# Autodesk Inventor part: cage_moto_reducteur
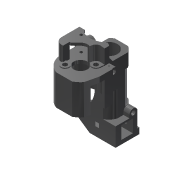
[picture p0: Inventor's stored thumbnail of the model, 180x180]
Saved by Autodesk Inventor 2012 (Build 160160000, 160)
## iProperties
Created: 2011-07
Part Number: cage_moto_reducteur
Document SubType Name: Modeling
Designer: didierf
Density: 1.13 g/cm^3
Material: Nylon - 6/6
Mass: 1.97671 g
Surface Area: 29.4498 cm^2
Volume: 1.7493 cm^3
entraxe_moteur_mobile: 6,000 mm
entraxe_mobile_roue_vis: 7,950 mm
entraxe_moteur_roue_vis: 12,000 mm
Author: didierf
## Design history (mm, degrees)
sketch "Esquisse1" dims "d1" = 12 (= 2 x entraxe_moteur_mobile), "d3" = 15.9 (= 2 x entraxe_mobile_roue_vis), "d4" = 24 (= 2 x entraxe_moteur_roue_vis)
  geometry: C1 r 2.5 at (2.847, -0.387); C2 r 0.5 at (-1.852, 3.344); C3 r 3.14 at (-9.14, 0.167); 3 further points
  constraints: 3 centre point, 3 coincident, 9 other
  dimensions: "d0" = 5 diameter of C1; "d2" = 1 diameter of C2; "d5" = 6.28 diameter of C3
sketch "Esquisse2" dims "d66" = 15.9 (= 2 x entraxe_mobile_roue_vis), "d67" = 12 (= 2 x entraxe_moteur_mobile), "d68" = 24 (= 2 x entraxe_moteur_roue_vis)
  geometry: L1 (-154.32, -14.987)-(-180.391, -5.63); L2 (-180.391, -5.63)-(-170.126, 22.971); L3 (-170.126, 22.971)-(-144.055, 13.613); L4 (-144.055, 13.613)-(-154.32, -14.987); L5 (-31.79, 28.076)-(-25.53, 28.076); L6 (-25.53, 28.076)-(-25.53, 27.076); L7 (-25.53, 27.076)-(-31.79, 27.076); L8 (-31.79, 27.076)-(-31.79, 28.076); L9 (-31.79, 28.076)-(-25.53, 27.076); L10 (-24.13, 32.056)-(-24.13, 23.306); L11 (-32.96, 32.056)-(-32.96, 23.306); L12 (-28.66, 27.576)-(-28.66, 30.706); L13 (-29.16, 24.446)-(-29.16, 30.706); L14 (-29.16, 30.706)-(-28.66, 30.706); L15 (-32.96, 32.056)-(-24.13, 32.056); L16 (-32.96, 23.306)-(-24.13, 23.306); L17 (-19.93, 38.152)-(-19.93, 8.926); L18 (-33.93, 33.977)-(-33.93, 8.926); L19 (-33.93, 8.926)-(-19.93, 8.926); L20 (-67.292, 19.43)-(-62.292, 19.43); L21 (-62.292, 19.43)-(-62.292, 18.43); L22 (-62.292, 18.43)-(-67.292, 18.43); L23 (-67.292, 18.43)-(-67.292, 19.43); L24 (-67.292, 19.43)-(-62.292, 18.43); L25 (-29.16, 24.446)-(-27.655, 24.446); C1 r 2.5 at (-60.831, 26.959); C2 r 0.5 at (-31.23, 20.052); C3 r 2.5 at (-27.128, 15.674); A1 r 3.17 centre (-28.66, 27.576) between (-31.79, 27.076) and (-29.16, 30.706); 4 further points
  constraints: 42 end point, 10 parallel, 7 perpendicular, 4 centre point, 3 coincident, 3 point on circle, 2 horizontal, 2 midpoint, 14 other
  dimensions: "d7" = 27.7 distance of L2.end L3.end; "d46" = 1 distance of L7.end L5.start; "d47" = 6.26 distance of L5.start L5.end; "d48" = 1.4 distance between parallel lines of L10 L6; "d49" = 8.83 distance between parallel lines of L11 L10; "d50" = 0.5 distance between parallel lines of L12 L13; "d51" = 1.35 distance between parallel lines of L15 L14; "d54" = 8.75 distance between parallel lines of L16 L15; "d55" = 4.2 distance between parallel lines of L17 L10; "d56" = 14 distance between parallel lines of L18 L17; "d58" = 23.13 distance between parallel lines of L19 L15; "d63" = 5 diameter of C1; "d64" = 5 distance of L21.end L22.end; "d65" = 1 distance of L20.end L21.end; "d69" = 2.7 distance from line of L18 C2.centre; "d275" = 5 diameter of C3; "d277" = 1 diameter of C2
  node "Image1"
sketch "Esquisse3"
  geometry: L1 (-32.96, 32.056)-(-24.13, 32.056) reference; L2 (-32.96, 32.056)-(-32.96, 23.306) reference; L3 (-32.96, 23.306)-(-24.13, 23.306) reference; L4 (-24.13, 32.056)-(-24.13, 23.306) reference
  dimensions: "d73" = 8.83 distance of L1.start L1.end (derived); "d74" = 8.75 distance of L1.start L2.end (derived)
extrude "corps_vis" new body sketch "Esquisse3" distance "d71" = 25.84; taper "d72" = 0 deg
sketch "Esquisse4"
  geometry: C1 r 3.175 at (-28.66, 27.576) reference
extrude "alésage roulements" cut sketch "Esquisse4" distance "d75" = 16.9; taper "d76" = 0 deg
sketch "Esquisse5"
  geometry: L1 (-24.13, 32.056)-(-24.13, 23.306) reference; L2 (-32.96, 32.056)-(-24.13, 32.056) reference; L3 (-32.96, 23.306)-(-32.96, 32.056) reference; L4 (-24.13, 23.306)-(-32.96, 23.306) reference; C1 r 3.17 at (-28.66, 27.576); C2 r 3 at (-28.66, 27.576); C3 r 3.175 at (-28.66, 27.576) reference
  constraints: 2 centre point, 1 coincident
  dimensions: "d289" = 6 diameter of C2
extrude "alésage butée roul" cut sketch "Esquisse5" distance "d79" = 19; taper "d80" = 0 deg
sketch "Esquisse6"
  geometry: L1 (-24.13, 32.056)-(-24.13, 23.306) reference; L2 (-32.96, 32.056)-(-24.13, 32.056) reference; L3 (-32.96, 23.306)-(-32.96, 32.056) reference; L4 (-24.13, 23.306)-(-32.96, 23.306) reference; C1 r 3.17 at (-28.66, 27.576); C2 r 1.98 at (-28.66, 27.576); C3 r 3.175 at (-28.66, 27.576) reference
  constraints: 2 centre point, 1 coincident
  dimensions: "d81" = 3.96 diameter of C2
extrude "alésage extrem vis" cut sketch "Esquisse6" stored distance "d82" = 19; taper "d83" = 0 deg
sketch "Esquisse9"
  geometry: L1 (0, 0)-(0, 25.84) reference; L2 (0, 25.84)-(0, 27.34); L3 (0, 27.34)-(-4, 27.34); L4 (-4, 27.34)-(-4, 0); L5 (0, 0)-(-4, 0)
  constraints: 8 end point, 2 perpendicular, 1 collinear, 1 parallel
  dimensions: "d91" = 4 distance between parallel lines of L4 L2; "d92" = 27.34 distance between parallel lines of L3 L5
extrude "platine_fixation" join sketch "Esquisse9" distance "d93" = 4; taper "d94" = 0 deg
sketch "Esquisse10"
  geometry: L1 (12.83, 0)-(4, 0) reference; L2 (2.832, -7.632)-(2.832, 0); L3 (16.832, -7.632)-(16.832, -2.75); L4 (7.552, -14.25)-(13.36, -14.25); L5 (4, 8.75)-(12.83, 8.75) reference; L6 (12.83, 8.75)-(12.83, 0) reference; L7 (12.83, 0)-(12.83, -0.757); L8 (16.832, -2.75)-(15.032, -2.75); L9 (15.032, -2.75)-(15.032, -2.227); L10 (4, 0)-(2.832, 0); L11 (9.832, -7.632)-(20.481, -7.632); L12 (16.832, -7.632)-(15.742, -12.25); C1 r 2.5 at (9.832, -7.632) reference; A1 r 7.5 centre (9.832, -7.632) between (13.36, -14.25) and (15.742, -12.25); A2 r 7 centre (9.832, -7.632) between (2.832, -7.632) and (7.552, -14.25); A3 r 7.5 centre (9.832, -7.632) between (15.032, -2.227) and (12.83, -0.757)
  constraints: 18 end point, 6 point on circle, 3 centre point, 3 perpendicular, 2 collinear, 2 parallel, 1 coincident, 1 point on line, 1 tangent
  dimensions: "d96" = 14 distance between parallel lines of L3 L2; "d97" = 23 distance between parallel lines of L4 L5; "d99" = 7.5 radius of A1; "d100" = 7 radius of A2; "d102" = 11.5 distance between parallel lines of L8 L4; "d103" = 7.5 radius of A3; "d104" = 1.8 distance between parallel lines of L3 L9; "d108" = 2 distance from line of L12.end L4
extrude "cage moteur" join sketch "Esquisse10" distance "d105" = 11.2; taper "d106" = 0 deg
sketch "Esquisse11" dims "d126" = 8
  geometry: L1 (5.232, -14.032)-(5.832, -14.032); L2 (5.832, -14.032)-(5.832, -11.632); L3 (5.832, -11.632)-(2.832, -11.632); L4 (2.832, -11.632)-(2.832, -14.032); L5 (14.332, -5.632)-(14.332, -7.321); L6 (15.032, -6.75)-(15.032, -6.227); L7 (7.552, -18.25)-(13.36, -18.25); L8 (16.832, -11.632)-(16.832, -6.75); L9 (2.832, -4)-(2.832, -11.632); L10 (5.832, -11.632)-(2.832, -11.632); L11 (12.83, -4.757)-(12.83, -4); L12 (9.832, -11.632)-(12.661, -8.803); L13 (12.834, -7.163)-(14.332, -7.321); L14 (9.773, -6.573)-(10.012, -9.138); L15 (11.045, -8.469)-(10.862, -9.354); L16 (4, 0)-(0, 0) reference; L17 (0, -4)-(0, 0) reference; L18 (2.832, -4)-(0, -4) reference; L19 (2.832, -4)-(2.832, -11.632) reference; L20 (7.552, -18.25)-(13.36, -18.25) reference; L21 (15.742, -16.25)-(16.832, -11.632) reference; L22 (16.832, -11.632)-(16.832, -6.75) reference; L23 (16.832, -6.75)-(15.032, -6.75) reference; L24 (15.032, -6.75)-(15.032, -6.227) reference; L25 (12.83, -4.757)-(12.83, -4) reference; L26 (12.83, -4)-(4, -4) reference; L27 (4, -4)-(4, 0) reference; C1 r 3.17 at (8.3, 0.27); C2 r 0.906 at (-111.833, -48.822); C3 r 0.735 at (-104.635, -44.629); C4 r 2.5 at (9.832, -11.632) reference; A1 r 2.4 centre (5.232, -11.632) between (2.832, -11.632) and (5.232, -14.032); A2 r 7.5 centre (9.832, -11.632) between (15.032, -6.227) and (12.83, -4.757); A3 r 1.65 centre (12.661, -8.803) between (12.834, -7.163) and (11.045, -8.469); A4 r 7 centre (9.832, -11.632) between (2.832, -11.632) and (5.832, -17.376); A5 r 7 centre (8.3, 0.27) between (9.773, -6.573) and (13.06, -4.862); A6 r 7.5 centre (9.832, -11.632) between (14.332, -5.632) and (13.06, -4.862); A7 r 2.5 centre (9.832, -11.632) between (10.012, -9.138) and (10.862, -9.354); A8 r 2.5 centre (9.832, -11.632) between (10.862, -9.354) and (10.012, -9.138); A9 r 7 centre (9.832, -11.632) between (2.832, -11.632) and (7.552, -18.25) reference; A10 r 7.5 centre (9.832, -11.632) between (13.36, -18.25) and (15.742, -16.25) reference; A11 r 7.5 centre (9.832, -11.632) between (15.032, -6.227) and (12.83, -4.757) reference
  constraints: 32 end point, 17 point on circle, 11 centre point, 5 coincident, 2 parallel, 2 perpendicular, 2 point on line, 2 tangent, 1 collinear, 1 horizontal, 3 other
  dimensions: "d114" = 2.5 distance between parallel lines of L8 L5; "d116" = 0 distance between parallel lines of L4 L9; "d117" = 3 distance of L2.end L3.end; "d118" = 2.4 distance of L3.end L4.end; "d119" = 2.4 distance between parallel lines of L10 L1; "d120" = 2.4 radius of A1; "d124" = 4.21821 distance between parallel lines of L1 L7; "d128" = 45 deg angle of L8 L12; "d129" = 3.3 diameter of A3; "d143" = 14 diameter of A5; "d144" = 1.68908 distance of L5.start L5.end
extrude "piliers" join sketch "Esquisse11" distance "d122" = 4.5; taper "d123" = 0 deg
sketch "Esquisse12"
  geometry: L1 (5.832, -11.632)-(6.332, -11.632); L2 (14.332, -7.321)-(12.834, -7.163) reference; L3 (5.832, -14.032)-(5.232, -14.032) reference; L4 (2.832, -11.632)-(2.832, -5.032); L5 (2.832, -5.032)-(4.832, -5.032); L6 (5.832, -11.632)-(5.832, -14.032) reference; L7 (14.332, -7.321)-(14.332, -5.632); L8 (6.332, -11.632)-(8.046, -9.882); L9 (13.06, -4.862)-(14.332, -5.632); L10 (11.045, -8.469)-(10.862, -9.354) reference; C1 r 3.17 at (8.3, 0.27) reference; A1 r 2.4 centre (5.232, -11.632) between (2.832, -11.632) and (5.232, -14.032) reference; A2 r 1.65 centre (12.661, -8.803) between (12.834, -7.163) and (11.045, -8.469) reference; A3 r 7 centre (8.3, 0.27) between (9.773, -6.573) and (13.06, -4.862) reference; A4 r 7 centre (8.3, 0.27) between (6.139, -6.388) and (13.06, -4.862); A5 r 7.5 centre (9.832, -11.632) between (14.332, -5.632) and (13.06, -4.862) reference; A6 r 2 centre (6.756, -4.486) between (4.832, -5.032) and (6.139, -6.388); A7 r 2.5 centre (9.832, -11.632) between (10.862, -9.354) and (10.012, -9.138) reference; A8 r 2.5 centre (9.832, -11.632) between (10.862, -9.354) and (8.046, -9.882); 1 further point
  constraints: 13 end point, 9 point on circle, 3 centre point, 3 tangent, 2 coincident, 1 horizontal, 1 parallel, 1 perpendicular, 1 point on line
  dimensions: "d133" = 0.5 distance of L1.start L1.end; "d137" = 9 distance between parallel lines of L5 L3; "d147" = 2 radius of A6; "d148" = 2 distance of L4.end L5.end
extrude "platine" join sketch "Esquisse12" distance "d138" = 1; taper "d139" = 0 deg
sketch "Esquisse14"
  geometry: L1 (-27.34, 0)-(-25.84, 0) reference; L2 (-25.84, 8.75)-(-25.84, 0) reference; L3 (-27.34, 0)-(-25.84, 1.1)
  constraints: 2 end point, 1 point on line
  dimensions: "d153" = 1.1 vertical distance of L1.start L3.end
extrude "chanfrein" join sketch "Esquisse14" stored distance "d154" = 1; taper "d155" = 0 deg
sketch "Esquisse13"
  geometry: L1 (0, 0)-(11.2, 0) reference; L2 (0, 0)-(0, 0.523) reference; L3 (1.5, 11.5)-(1.5, 3.85) reference; L4 (0, 0.523)-(11.2, 0.523) reference; L5 (4.45, 0.523)-(1.55, 0.523); L6 (4.45, 2.1)-(4.45, 0.523); L7 (4.45, 0)-(4.45, -0.154); L8 (1.55, 2.1)-(1.55, 0.523); L9 (1.05, 0)-(1.05, -0.345); L10 (27.34, 11.5)-(1.5, 11.5) reference; L11 (27.34, 11.5)-(27.34, 2.75) reference; L12 (27.34, 2.75)-(11.2, 2.75) reference; L13 (20.54, 2.75)-(20.54, 7.85); L14 (19.5, 7.85)-(20.54, 7.85); L15 (25.19, 10.75)-(19.5, 10.75); L16 (20.54, 2.75)-(27.34, 2.75); L17 (27.34, 2.75)-(27.34, 10.75); L18 (25.19, 10.75)-(25.19, 11.5); L19 (25.19, 11.5)-(27.34, 11.5); L20 (27.34, 11.5)-(27.34, 10.75); C1 r 0.9 at (3, 2.1); C2 r 0.9 at (19.5, 9.3); A1 r 1.45 centre (3, 2.1) between (4.45, 2.1) and (1.55, 2.1); A2 r 1.45 centre (19.5, 9.3) between (19.5, 10.75) and (19.5, 7.85)
  constraints: 26 end point, 8 point on line, 7 parallel, 5 point on circle, 5 tangent, 4 centre point, 4 collinear, 3 perpendicular, 2 coincident
  dimensions: "d149" = 2.1 distance from line of A1.centre L1; "d151" = 2.9 diameter of A1; "d152" = 1.8 diameter of C1; "d156" = 1.5 distance from line of L3 C1.centre; "d159" = 16.5 horizontal distance of C1.centre C2.centre; "d161" = 1.8 diameter of C2; "d162" = 6.8 distance between parallel lines of L13 L11; "d163" = 0.75 distance between parallel lines of L15 L10; "d164" = 1.45 radius of A2; "d263" = 2.15 distance between parallel lines of L20 L18
extrude "bossages" join sketch "Esquisse13" stored distance "d157" = 1; taper "d158" = 0 deg
sketch "Esquisse15"
  geometry: C1 r 0.8 at (3, 2.1); C2 r 0.8 at (19.5, 9.3); A1 r 1.45 centre (19.5, 9.3) between (19.5, 10.75) and (19.5, 7.85) reference; A2 r 1.45 centre (3, 2.1) between (4.45, 2.1) and (1.55, 2.1) reference
  constraints: 2 centre point, 2 coincident
  dimensions: "d165" = 1.6 diameter of C2; "d166" = 1.6 diameter of C1 (derived)
extrude "perçage bossage" cut sketch "Esquisse15" distance "d167" = 3; taper "d168" = 0 deg
sketch "Esquisse17"
  geometry: L1 (11.2, -2.618)-(2, -2.618); L2 (2, -2.618)-(2, 1.882); L3 (2, 1.882)-(11.2, 1.882); L4 (11.2, 1.882)-(11.2, -2.618); L5 (0, -6.618)-(11.2, -6.618) reference; L6 (0, 0)-(0, 4.882) reference; L7 (11.2, 0)-(11.2, 4.882) reference
  constraints: 8 end point, 2 parallel, 1 collinear, 1 horizontal, 1 perpendicular
  dimensions: "d172" = 4 distance between parallel lines of L5 L1; "d173" = 4.5 distance of L3.end L1.start; "d174" = 2 distance between parallel lines of L2 L6
extrude "fenetre log moteur" cut sketch "Esquisse17" distance "d175" = 5; taper "d176" = 0 deg
sketch "Esquisse16"
  geometry: C1 r 2.5 at (-9.832, -7.632) reference; C2 r 6.25 at (-9.832, -7.632)
  constraints: 1 centre point, 1 coincident
  dimensions: "d169" = 12.5 diameter of C2
extrude "log moteur" cut sketch "Esquisse16" distance "d170" = 10; taper "d171" = 0 deg
sketch "Esquisse18"
  geometry: L1 (-12.83, 8.75)-(-12.83, 1.1); L2 (-12.83, 1.1)-(-12.83, 0); L3 (-12.83, -0.757)-(-12.83, 0); L4 (-12.83, -0.757)-(-12.83, -0.75); L5 (-12.83, -0.75)-(-12.83, -0.75); L6 (-12.83, -0.75)-(-12.83, -0.757); L7 (-12.83, -0.757)-(-12.83, 0); L8 (-12.83, 0)-(-12.83, 5.1); L9 (-12.83, 5.1)-(-12.83, 8); L10 (-12.83, 0)-(-2.832, 0); L11 (-12.83, 8)-(-12.83, 8.75); L12 (-15.507, -10.25)-(-16.214, -10.25) reference; L13 (-15.742, -12.25)-(-16.214, -10.25) reference; L14 (-7.552, -14.25)-(-13.36, -14.25) reference; L15 (-2.832, 0)-(-2.832, -7.632) reference; L16 (-12.83, 0)-(-2.832, 0) reference; L17 (-12.83, -0.757)-(-12.83, 0) reference; L18 (-15.032, -2.75)-(-15.032, -2.227) reference; L19 (-16.832, -2.75)-(-15.032, -2.75) reference; L20 (-16.832, -5.75)-(-16.832, -2.75) reference; L21 (-16.832, -5.75)-(-15.792, -5.75) reference; C1 r 3.17 at (-8.3, 4.27); A1 r 4.75 centre (-8.3, 4.27) between (-12.83, 2.841) and (-10.381, 0); A2 r 6.25 centre (-9.832, -7.632) between (-15.507, -10.25) and (-15.792, -5.75) reference; A3 r 7.5 centre (-9.832, -7.632) between (-15.742, -12.25) and (-13.36, -14.25) reference; A4 r 7 centre (-9.832, -7.632) between (-7.552, -14.25) and (-2.832, -7.632) reference; A5 r 7.5 centre (-9.832, -7.632) between (-12.83, -0.757) and (-15.032, -2.227) reference
  constraints: 22 end point, 2 centre point, 2 point on circle, 2 point on line, 1 coincident
extrude "forme extrne 1" cut sketch "Esquisse18" stored distance "d178" = 5; taper "d179" = 0 deg
node "Plan de construction2"
sketch "Esquisse19"
  geometry: L1 (-1.168, -27.34)-(-4, -27.34) reference; L2 (-4, -27.34)-(-4, 0) reference; L3 (11.032, 0)-(-4, 0) reference; L4 (-5.57, -14.935)-(17.224, -14.935); L5 (8.83, -16.14)-(8.83, -6.8) reference; L6 (3.43, -6.833)-(3.43, -13.539); L7 (-4, -4.84)-(-4, -25.34); L8 (-3.129, -3.189)-(1.532, 0); L9 (1.532, 0)-(-4, 0); L10 (-4, -25.34)-(-4, -27.34); L11 (-4, -27.34)-(-2, -27.34); A1 r 2 centre (-2, -25.34) between (-2.649, -23.448) and (-2, -27.34); A2 r 2 centre (-2, -4.84) between (-1.688, -6.816) and (-3.484, -6.18); A3 r 9 centre (-5.57, -14.935) between (-2.649, -23.448) and (-3.484, -6.18)
  constraints: 14 end point, 10 point on circle, 8 tangent, 4 point on line, 3 centre point, 2 collinear, 2 parallel, 1 perpendicular
  dimensions: "d181" = 4 diameter of A1; "d182" = 4 diameter of A2; "d183" = 18 diameter of A3; "d184" = 20.5 distance of A2.centre A1.centre; "d185" = 5.4 distance between parallel lines of L6 L5; "d186" = 9.5 distance of L3.start L8.end
extrude "debouchage engrenage" cut sketch "Esquisse19" stored distance "d187" = 5; taper "d188" = 0 deg; taper "d254" = 0 deg
sketch "Esquisse22"
  geometry: L1 (0, -27.34)-(-2, -27.34) reference; L2 (0, -25.84)-(0, -27.34) reference; L3 (0, -22.005)-(0, -25.84) reference; L4 (0, -1.048)-(0, -7.866) reference; L5 (0, -1.048)-(-3.129, -3.189) reference; A1 r 9 centre (-5.57, -14.935) between (-2.649, -23.448) and (0, -22.005) reference; A2 r 2 centre (-2, -25.34) between (-2.649, -23.448) and (-2, -27.34) reference; A3 r 9 centre (-5.57, -14.935) between (0, -7.866) and (-3.484, -6.18) reference; A4 r 2 centre (-2, -4.84) between (-3.129, -3.189) and (-3.484, -6.18) reference
extrude "correction" cut sketch "Esquisse22" distance "d191" = 0.7; taper "d192" = 0 deg
sketch "Esquisse23"
  geometry: C1 r 1.7 at (-2, -25.34); C2 r 1.7 at (-2, -4.84); A1 r 2 centre (-2, -25.34) between (-2.649, -23.448) and (-2, -27.34) reference; A2 r 2 centre (-2, -4.84) between (-3.129, -3.189) and (-3.484, -6.18) reference
  constraints: 2 centre point, 2 coincident
  dimensions: "d193" = 3.4 diameter of C1; "d194" = 3.4 diameter of C2
extrude "bossages2" join sketch "Esquisse23" distance "d195" = 1; taper "d196" = 0 deg
sketch "Esquisse24"
  geometry: C1 r 1.7 at (0, 0) reference; C2 r 1.7 at (0, 20.5) reference; C3 r 1 at (0, 0); C4 r 1 at (0, 20.5)
  constraints: 2 centre point, 2 coincident
  dimensions: "d197" = 2 diameter of C3; "d198" = 2 diameter of C4
extrude "trous bossages2" cut sketch "Esquisse24" stored distance "d199" = 1; taper "d200" = 0 deg
sketch "Esquisse25"
  geometry: A1 r 9 centre (-3.57, -9.995) between (-0.084, -1.698) and (-1.011, -1.367) reference; A2 r 1.7 centre (0, 0) between (-0.084, -1.698) and (-1.011, -1.367) reference
extrude "correction2" cut sketch "Esquisse25" stored distance "d201" = 1; taper "d202" = 0 deg
sketch "Esquisse27"
  geometry: L1 (-32.96, 26.606)-(-32.96, 32.056); L2 (-32.96, 32.056)-(-24.13, 32.056); L3 (-32.96, 30.127)-(-32.96, 32.056); L4 (-32.96, 32.056)-(-30.88, 32.056); L5 (-32.96, 24.406)-(-28.838, 24.406) reference; L6 (-28.482, 24.406)-(-24.13, 24.406) reference; L7 (-24.13, 32.056)-(-24.13, 24.406) reference; L8 (-32.96, 32.056)-(-24.13, 32.056) reference; L9 (-32.96, 26.606)-(-32.96, 32.056) reference; L10 (-32.96, 24.406)-(-32.96, 26.606) reference; C1 r 3.17 at (-28.66, 27.576); A1 r 5 centre (-28.66, 27.576) between (-32.96, 30.127) and (-30.88, 32.056); A2 r 3.175 centre (-28.66, 27.576) between (-28.482, 24.406) and (-28.838, 24.406) reference
  constraints: 8 end point, 2 centre point, 2 point on circle, 2 point on line, 1 coincident, 1 collinear
  dimensions: "d210" = 10 diameter of A1
extrude "forme externe 2" cut sketch "Esquisse27" stored distance "d211" = 10; taper "d212" = 0 deg
node "Plan de construction3"
node "Plan de construction6"
sketch "Esquisse26"
  geometry: L1 (-30.88, 32.056)-(-24.13, 32.056); L2 (-32.96, 26.606)-(-32.96, 30.127); L3 (-27.081, 32.056)-(-24.13, 32.056); L4 (-24.13, 32.056)-(-24.13, 29.004); C1 r 3.17 at (-28.66, 27.576); A1 r 4.75 centre (-28.66, 27.576) between (-24.13, 29.004) and (-27.081, 32.056); 1 further point
  constraints: 8 end point, 2 centre point, 2 point on circle, 1 coincident, 1 collinear, 1 perpendicular, 1 point on line
  dimensions: "d206" = 9.5 diameter of A1
extrude "forme externe 3" cut sketch "Esquisse26" stored distance "d213" = 10; taper "d214" = 0 deg
sketch "Esquisse29"
  geometry: L1 (-30.88, 32.056)-(-24.13, 32.056) reference; L2 (-24.13, 32.056)-(-24.13, 24.406) reference; L3 (-24.13, 32.056)-(-26.12, 32.056); L4 (-24.13, 32.056)-(-24.13, 30.025); C1 r 3.17 at (-28.66, 27.576) reference; A1 r 4.75 centre (-28.66, 27.576) between (-24.13, 29.004) and (-27.081, 32.056) reference; A2 r 5.15 centre (-28.66, 27.576) between (-24.13, 30.025) and (-26.12, 32.056)
  constraints: 4 end point, 2 point on circle, 2 point on line, 1 centre point, 1 coincident
  dimensions: "d217" = 0.4 radial gap between concentric circles of A2 A1
extrude "forme externe 4" cut sketch "Esquisse29" stored distance "d218" = 18; taper "d219" = 0 deg
sketch "Esquisse30"
  geometry: L1 (2.48, 0)-(1.822, 0) reference; L2 (1.04, 1.28)-(0, 1.28) reference; L3 (0, 1.28)-(0, 0) reference; L4 (0.258, 0)-(0, 0) reference; A1 r 1.45 centre (1.04, -0.17) between (2.48, 0) and (1.04, 1.28) reference; A2 r 0.8 centre (1.04, -0.17) between (1.822, 0) and (0.258, 0) reference
extrude "bouchage forme externe 4" join sketch "Esquisse30" stored distance "d221" = 18; taper "d222" = 0 deg
sketch "Esquisse31"
  geometry: C1 r 1.7 at (-4.08, -25.34) reference; 2 further points
  constraints: 1 coincident, 3 other
extrude "marque éject" cut sketch "Esquisse31" stored distance "d224" = 18; taper "d225" = 0 deg
sketch "Esquisse32"
  geometry: L1 (0.784, -25.84)-(0, -25.84) reference; L2 (0, -27.34)-(-2, -27.34) reference; L3 (0, -25.84)-(-0.064, -25.84); L4 (0, -27.34)-(0, -25.84); L5 (0, -27.34)-(-2, -27.34); A1 r 2.828 centre (-2, -25.34) between (0.784, -25.84) and (0, -23.34) reference; A2 r 2 centre (-2, -25.34) between (-2, -27.34) and (-0.064, -25.84); 3 further points
  constraints: 7 end point, 2 coincident, 2 perpendicular, 2 point on circle, 2 point on line, 1 centre point, 1 tangent, 4 other
extrude "marque éject2" cut sketch "Esquisse32" stored distance "d226" = 18; taper "d227" = 0 deg
sketch "Esquisse33"
  geometry: L1 (-4.72, 0)-(-4.02, -0.7); L2 (-4.02, -0.7)-(-4.02, -5); L3 (-4.02, -5)-(-4.72, -5); L4 (-4.72, 0)-(-4.72, -5); L5 (-4.72, -11.2)-(-0.203, -11.2) reference; L6 (2.829, -11.2)-(-0.203, -11.2) reference; L7 (2.829, -11.2)-(5.278, -11.2) reference; L8 (7.48, -11.2)-(5.278, -11.2) reference; L9 (9.28, -11.2)-(7.48, -11.2) reference; L10 (9.28, -11.2)-(8.24, -11.2) reference; L11 (8.24, -11.2)-(7.955, -11.2) reference; L12 (7.955, -11.2)-(8.662, -11.2) reference; L13 (8.19, -11.2)-(8.662, -11.2) reference; L14 (5.809, -11.2)-(8.19, -11.2) reference; L15 (0, -11.2)-(5.809, -11.2) reference; L16 (-4.72, -11.2)-(0, -11.2) reference; L17 (-2.36, -11.2)-(-4.72, -11.2); L18 (-4.72, -11.2)-(-4.72, -9.637); L19 (-10.786, -18.006)-(-11.532, -18.006); A1 r 9 centre (-9.122, -12.405) between (-7.036, -21.16) and (-0.203, -11.2) reference; A2 r 5.2 centre (-9.122, -12.405) between (-4.063, -11.2) and (-4.72, -9.637)
  constraints: 14 end point, 4 perpendicular, 2 point on circle, 1 centre point, 1 coincident, 1 collinear, 1 midpoint, 1 point on line, 1 vertical
  dimensions: "d228" = 0.7 distance between parallel lines of L2 L4; "d229" = 5 distance from line of L3 L1.start; "d230" = 45 deg angle of L3 L1; "d233" = 3.8 radial gap between concentric circles of A1 A2
extrude "dégagement arrière" cut sketch "Esquisse33" stored distance "d231" = 18; taper "d232" = 0 deg
node "Plan de construction9"
  node "Plan de construction8"
sketch "Esquisse34"
  geometry: L1 (24.335, 27.576)-(24.335, 32.056); L2 (32.985, 27.576)-(32.985, 32.056); L3 (30.88, 32.056)-(26.12, 32.056) reference; L4 (32.985, 32.056)-(24.335, 32.056); C1 r 1.98 at (28.66, 27.576) reference; A1 r 4.325 centre (28.66, 27.576) between (24.335, 27.576) and (32.985, 27.576)
  constraints: 6 end point, 2 point on circle, 2 tangent, 1 centre point, 1 coincident, 1 collinear, 1 parallel, 1 perpendicular, 1 vertical
  dimensions: "d236" = 8.65 diameter of A1
extrude "ouverture1" cut sketch "Esquisse34" stored distance "d237" = 18; taper "d238" = 0 deg
node "Plan de construction11"
  node "Plan de construction10"
sketch "Esquisse35"
  geometry: L1 (26.68, 27.576)-(26.68, 32.056); L2 (30.88, 32.056)-(24.335, 32.056) reference; L3 (30.64, 32.056)-(26.68, 32.056); L4 (32.96, 27.111)-(32.96, 30.127) reference; L5 (30.64, 27.576)-(30.64, 32.056); A1 r 1.98 centre (28.66, 27.576) between (30.64, 27.576) and (26.68, 27.576) reference; A2 r 1.98 centre (28.66, 27.576) between (26.68, 27.576) and (30.386, 26.606); 4 further points; 1 other entity
  constraints: 6 end point, 4 point on circle, 3 point on line, 2 parallel, 2 tangent, 1 centre point, 1 coincident, 1 concentric, 1 horizontal alignment
extrude "ouverture2" cut sketch "Esquisse35" stored distance "d241" = 18; taper "d242" = 0 deg
sketch "Esquisse38"
  geometry: L1 (4.2, -6.15)-(0.24, -6.15) reference; L2 (4.2, -6.84)-(0.24, -6.84) reference; L3 (0.24, -6.15)-(0.24, -4.7) reference; L4 (-2.08, -3.2)-(2.22, -3.2); L5 (2.22, -6.15)-(2.22, -3.2); L6 (2.22, -6.15)-(-2.08, -6.15); L7 (-2.08, -7.866)-(-2.08, -1.048) reference; L8 (-2.08, -6.15)-(-2.08, -3.2); 2 further points
  constraints: 8 end point, 2 perpendicular, 2 point on line, 1 collinear, 1 midpoint, 1 parallel
extrude "ouverture3" cut sketch "Esquisse38" stored distance "d246" = 0.8; taper "d247" = 0 deg
sketch "Esquisse36"
  geometry: L1 (26.68, 27.576)-(26.68, 32.056) reference; L2 (26.68, 32.056)-(30.64, 32.056) reference; L3 (27.68, 32.056)-(27.68, 29.296); A1 r 1.98 centre (28.66, 27.576) between (30.64, 27.576) and (26.68, 27.576) reference; 2 further points
  constraints: 2 end point, 1 perpendicular, 1 point on circle, 1 point on line
  dimensions: "d243" = 1 distance between parallel lines of L3 L1
extrude "bouchage" join sketch "Esquisse36" distance "d244" = 0.8; taper "d245" = 0 deg
sketch "Esquisse37"
  geometry: L1 (0.24, -2.15)-(4.2, -2.15) reference; L2 (6.75, -2.15)-(6.75, -6.8) reference; L3 (2.22, -2.15)-(2.22, -6.15); L4 (5.771, -7.84)-(5.771, -6.8) reference; L5 (3.2, -6.15)-(0, -6.15) reference; L6 (2.22, -6.15)-(5.771, -6.15); L7 (5.771, -6.15)-(5.771, -6.8); L8 (6.75, -6.8)-(6.75, -2.15); L9 (6.75, -2.15)-(2.22, -2.15); L10 (5.771, -6.8)-(6.75, -6.8); 2 further points
  constraints: 13 end point, 2 parallel, 2 perpendicular, 1 collinear, 1 midpoint, 1 point on line
extrude "forme extene 5" cut sketch "Esquisse37" stored distance "d248" = 0.8; taper "d249" = 0 deg
sketch "Esquisse39"
  geometry: L1 (1.011, -0.75)-(1.011, 0) reference; L2 (0, 0)-(1.011, 0) reference; A1 r 5.15 centre (-2.54, -4.48) between (1.011, -0.75) and (0, 0) reference
extrude "forme extene 6" cut sketch "Esquisse39" stored distance "d250" = 0.8; taper "d251" = 0 deg
sketch "Esquisse40"
  geometry: L1 (5.57, 7.069)-(5.57, 8.785) reference; L2 (5.57, 8.785)-(7.65, 8.785) reference; L3 (5.57, 8.136)-(5.57, 8.785); L4 (5.57, 8.785)-(6.045, 8.785); C1 r 1 at (3.57, 10.095) reference; A1 r 2.8 centre (3.57, 10.095) between (5.57, 8.136) and (6.045, 8.785)
  constraints: 4 end point, 2 point on circle, 2 point on line, 1 centre point, 1 coincident, 1 perpendicular
  dimensions: "d252" = 5.6 diameter of A1
extrude "marque ejec 2" cut sketch "Esquisse40" stored distance "d253" = 0.8; taper "d254" = 0 deg
sketch "Esquisse41"
  geometry: L1 (21.19, 6.05)-(21.19, 10.24) reference; L2 (21.19, 11.5)-(21.19, 10.24) reference; L3 (21.19, 11.5)-(21.19, 10.75) reference; L4 (21.19, 10.75)-(21.19, 8.74) reference; L5 (21.19, 6.05)-(21.19, 8.74) reference; L6 (25.89, 9.1)-(25.89, 4.9); L7 (25.19, 10.75)-(19.5, 10.75) reference; L8 (25.89, 9.1)-(21.19, 9.1); L9 (20.54, 2.75)-(27.34, 2.75) reference; L10 (21.19, 9.1)-(21.19, 4.9); L11 (21.19, 4.9)-(25.89, 4.9); L12 (27.34, 2.75)-(27.34, 11.5) reference
  constraints: 8 end point, 3 parallel, 1 perpendicular, 1 point on line
  dimensions: "d256" = 1.65 distance between parallel lines of L7 L8; "d258" = 2.15 distance between parallel lines of L11 L9; "d264" = 1.45 distance between parallel lines of L12 L6
extrude "ouverture arriere" cut sketch "Esquisse41" distance "d259" = 4.7; taper "d260" = 0 deg
sketch "Esquisse43"
  geometry: L1 (26.088, 30.156)-(31.188, 30.156); L2 (31.188, 30.156)-(31.188, 25.056); L3 (31.188, 25.056)-(26.088, 25.056); L4 (26.088, 25.056)-(26.088, 30.156); L5 (21.928, 23.306)-(31.428, 23.306) reference; L6 (21.928, 23.306)-(21.928, 32.056) reference
  constraints: 8 end point, 2 parallel, 1 horizontal, 1 perpendicular
  dimensions: "d265" = 1.75 distance between parallel lines of L5 L3; "d266" = 4.16 distance between parallel lines of L4 L6; "d267" = 5.1 distance between parallel lines of L2 L4; "d268" = 5.1 distance between parallel lines of L1 L3
extrude "logement lateral" cut sketch "Esquisse43" distance "d269" = 1.1; taper "d270" = 0 deg
sketch "Esquisse44"
  geometry: C1 r 0.5 at (5.73, -7.253) reference; C2 r 0.5 at (5.73, -7.253)
  constraints: 1 centre point, 1 coincident
  dimensions: "d271" = 1 diameter of C2
extrude "perçage axe mobile" cut sketch "Esquisse44" stored distance "d272" = 1.1; taper "d273" = 0 deg
sketch "Esquisse45"
  geometry: L1 (5.109, 9.447)-(2.28, 6.618); L2 (2.28, 6.618)-(-1.399, 2.94); L3 (-2.048, 3.79)-(-2.048, 4.218); L4 (-4.72, 14.25)-(-4.72, 6.618) reference; L5 (-2.32, 4.218)-(-1.72, 4.218) reference; L6 (-1.72, 6.618)-(-1.72, 4.218) reference; L7 (-0.548, 5.29)-(-1.72, 5.29); L8 (0, 0)-(5.809, 0) reference; L9 (6.78, 10.929)-(6.6, 9.283); L10 (-1.72, 4.218)-(-2.32, 4.218) reference; L11 (-2.048, 4.218)-(-1.72, 4.218); L12 (-1.72, 4.218)-(-1.72, 5.29); L13 (3.493, 9.781)-(3.31, 8.896) reference; L14 (6.78, 10.929)-(5.282, 11.087) reference; A1 r 2.5 centre (2.28, 6.618) between (2.46, 9.112) and (3.31, 8.896) reference; A2 r 1.5 centre (-0.548, 3.79) between (-2.048, 3.79) and (-0.548, 5.29); A3 r 1.5 centre (5.109, 9.447) between (4.048, 8.386) and (6.6, 9.283); A4 r 2.5 centre (2.28, 6.618) between (4.048, 8.386) and (3.31, 8.896); A5 r 2.5 centre (2.28, 6.618) between (4.048, 8.386) and (3.31, 8.896); A6 r 1.65 centre (5.109, 9.447) between (5.282, 11.087) and (3.493, 9.781) reference; 6 further points
  constraints: 14 end point, 9 point on circle, 5 coincident, 4 centre point, 3 collinear, 3 midpoint, 3 tangent, 2 parallel, 2 point on line, 3 other
  dimensions: "d281" = 3 diameter of A2; "d282" = 3 diameter of A3
extrude "fixation moteur bossage" join sketch "Esquisse45" distance "d279" = 0.3; taper "d280" = 0 deg
sketch "Esquisse46"
  geometry: C1 r 0.8 at (-0.548, 3.79); C2 r 0.8 at (5.109, 9.447); A1 r 1.5 centre (-0.548, 3.79) between (-2.048, 3.79) and (-0.548, 5.29) reference; A2 r 1.5 centre (5.109, 9.447) between (4.048, 8.386) and (6.6, 9.283) reference
  constraints: 2 centre point, 2 coincident
  dimensions: "d283" = 1.6 diameter of C2; "d284" = 1.6 diameter of C1
extrude "fixation moteur trous" cut sketch "Esquisse46" stored distance "d285" = 1.1; taper "d286" = 0 deg
node "Solide1"
node "Corps solides"
node "Corps surfaciques"
node "Boucle projetée3"
node "Boucle projetée4"
node "Boucle projetée5"
node "Boucle projetée6"
node "Boucle projetée7"
node "Boucle projetée8"
node "Boucle projetée9"
node "Référence1"
other parameters: "entraxe_moteur_mobile" = 6 [user parameter; used in 2 equation terms], "entraxe_mobile_roue_vis" = 7.95 [user parameter; used in 2 equation terms], "entraxe_moteur_roue_vis" = 12 [user parameter; used in 2 equation terms], "d95" = 15, "d98" = 7.5, "d101" = 7.5, "d136" = 9, "d177" = 9.5, "d180" = -10.3, "d203" = -4.8, "d205" = -16.5, "d234" = -3.2, "d235" = -1.5, "d239" = -2.15, "d240" = -4, "d257" = 2.2
